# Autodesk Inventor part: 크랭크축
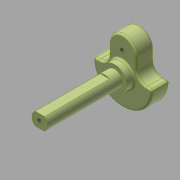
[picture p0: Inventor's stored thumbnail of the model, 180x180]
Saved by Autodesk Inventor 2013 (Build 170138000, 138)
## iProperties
Created: 2018-01
Part Number: 크랭크축
Material: 강철, 탄소
Document SubType Name: Modeling
Designer: mduedu
Density: 1 g/cm^3
Author: mduedu
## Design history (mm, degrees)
sketch "스케치1"
  geometry: L1 (-15, 0)-(15, 0); L2 (-7, 0)-(7, 0); L3 (7, 0)-(7, 10); L4 (-7, 10)-(-7, 0); A1 r 15 centre (0, 0) between (-15, 0) and (15, 0); A2 r 7 centre (0, 10) between (7, 10) and (-7, 10); 3 further points
  constraints: 8 end point, 4 point on circle, 3 coincident, 2 centre point, 2 horizontal, 2 midpoint, 2 tangent, 1 parallel, 1 perpendicular, 1 point on line
  dimensions: "d0" = 30 diameter of A1; "d1" = 17 dimension on A2 L1; "d2" = 7 radius of A2
extrude "돌출1" new body sketch "스케치1" distance "d4" = 9; taper "d5" = 0 deg
sketch "스케치2"
  geometry: C1 r 6 at (0, 0); 1 further point
  constraints: 1 centre point, 1 coincident
  dimensions: "d6" = 12 diameter of C1
extrude "돌출2" join sketch "스케치2" distance "d7" = 4; taper "d8" = 0 deg
sketch "스케치3"
  geometry: C1 r 4 at (0, 0); 1 further point
  constraints: 1 centre point, 1 coincident
  dimensions: "d9" = 8 diameter of C1
extrude "돌출3" join sketch "스케치3" distance "d10" = 38; taper "d11" = 0 deg
sketch "스케치4"
  geometry: L1 (-2.332, 3.25)-(2.332, 3.25); L2 (-2.332, -3.25)-(2.332, -3.25); A1 r 4 centre (0, 0) between (-2.332, 3.25) and (2.332, 3.25) reference; A2 r 4 centre (0, 0) between (2.332, 3.25) and (-2.332, 3.25); A3 r 4 centre (0, 0) between (-2.332, -3.25) and (2.332, -3.25); 1 further point
  constraints: 8 point on circle, 4 end point, 2 centre point, 2 coincident, 2 parallel, 1 horizontal
  dimensions: "d12" = 6.5 distance between parallel lines of L2 L1
extrude "돌출4" cut sketch "스케치4" distance "d13" = 33; taper "d14" = 0 deg
fillet "모깎기1" dims "d15" = 5
fillet "모깎기2" dims "d16" = 1
fillet "모깎기3" dims "d17" = 1
fillet "모깎기4" dims "d18" = 1
sketch "스케치5"
  geometry: 1 further point
  constraints: 1 other
hole "구멍1" sketch "스케치5" at (0, 10) diameter "d19" = 2.459; stored, may be unused: countersink angle "d23" = 90 deg, drill point angle "d25" = 120 deg; dims "d20" = 10, "d21" = 4, "d22" = 2, "d24" = 11.5
sketch "스케치6"
  geometry: 1 further point
  constraints: 1 other
hole "구멍2" sketch "스케치6" at (0, 0) diameter "d26" = 2.459; stored, may be unused: countersink angle "d30" = 90 deg, drill point angle "d32" = 120 deg; dims "d27" = 12.7, "d28" = 4, "d29" = 2, "d31" = 14.2
node "솔리드1"
node "투영된 루프1"
